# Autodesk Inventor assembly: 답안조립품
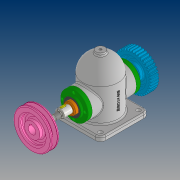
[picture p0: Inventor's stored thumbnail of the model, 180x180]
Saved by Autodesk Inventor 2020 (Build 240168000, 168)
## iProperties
Created: 2021-08
Part Number: 답안조립품
Document SubType Name: Assembly
Designer: PC312-
Author: PC312-
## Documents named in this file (11)
- C:\Users\PC312-\Desktop\710809V1006\답안조립품.iam
- C:\Users\PC312-\Desktop\710809V1006\본체.ipt
- C:\Users\PC312-\Desktop\710809V1006\축.ipt
- C:\Users\PC312-\Desktop\710809V1006\베어링 6203.ipt
- C:\Users\PC312-\Desktop\710809V1006\부시.ipt
- C:\Users\PC312-\Desktop\710809V1006\커버.ipt
- C:\Users\PC312-\Desktop\710809V1006\오일 실 26 38 8.ipt
- C:\Users\PC312-\Desktop\710809V1006\스퍼기어.ipt
- C:\Users\PC312-\Desktop\710809V1006\V-벨트풀리.ipt
- V-벨트풀리.ipt
- C:\Users\PC312-\Desktop\710809V1006\키 5x5x12.ipt
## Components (1 placed, 1 different names)
1. V-벨트풀리:1
